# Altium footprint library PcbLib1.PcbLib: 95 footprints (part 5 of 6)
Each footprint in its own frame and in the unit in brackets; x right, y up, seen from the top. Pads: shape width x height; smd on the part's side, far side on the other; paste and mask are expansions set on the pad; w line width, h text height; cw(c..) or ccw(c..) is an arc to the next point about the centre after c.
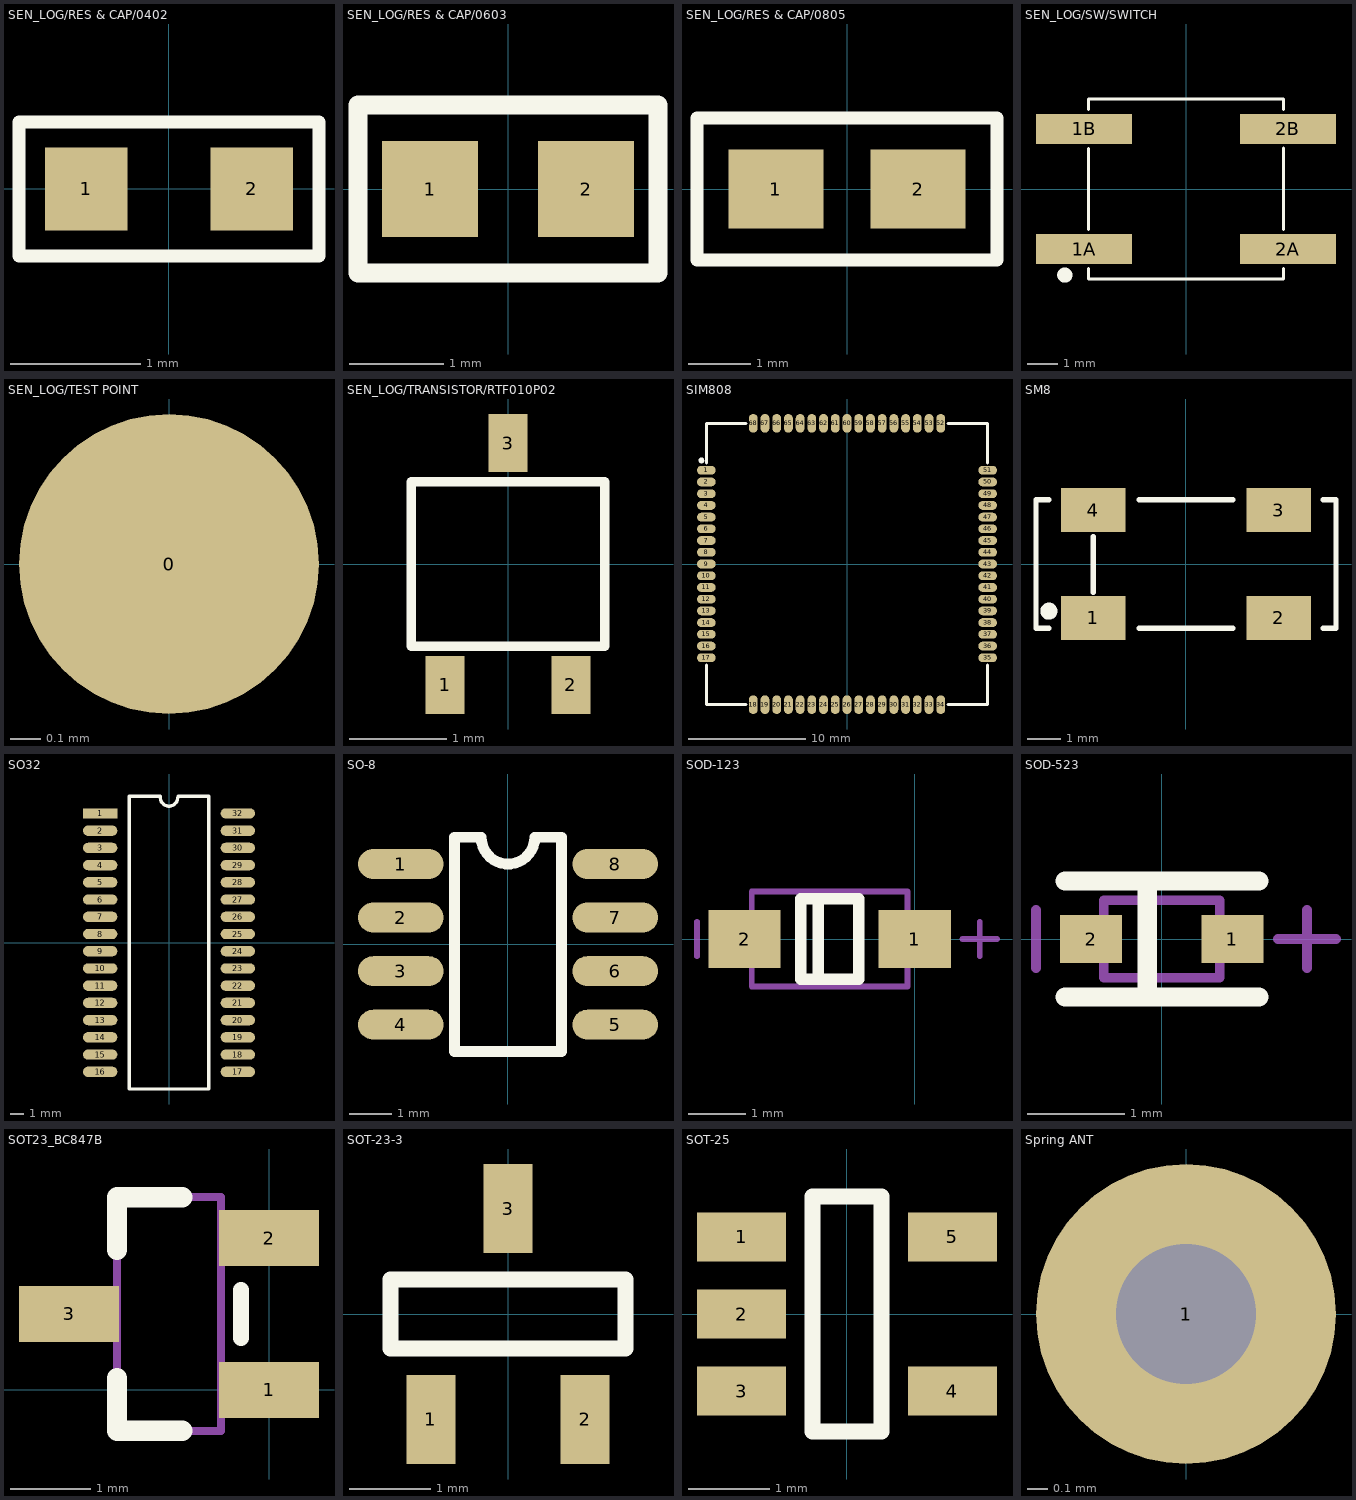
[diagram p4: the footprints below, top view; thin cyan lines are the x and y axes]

## SEN_LOG/RES & CAP/0402 [mm]
pads (2):
  rect 0.635x0.635 smd: 1(-0.635,0) 2(0.635,0)
Top Overlay:
  lines w0.1: -1.15,-0.513 -1.15,0.512 1.15,0.512 1.15,-0.513 -1.15,-0.513

## SEN_LOG/RES & CAP/0603 [mil]
pads (2):
  rect 40x40 smd: 1(-32.5,0) 2(32.5,0)
Top Overlay:
  lines w8: -62.5,-35 -62.5,35 62.5,35 62.5,-35 -62.5,-35

## SEN_LOG/RES & CAP/0805 [mil]
pads (2):
  rect 60x50 smd: 1(-45,0) 2(45,0)
Top Overlay:
  lines w8: 20,45 95,45 95,-45 20,-45 -95,-45 -95,45 25,45

## SEN_LOG/SW/SWITCH [mm]
pads (4):
  rect 3.2x1 smd mask+0.07: 1A(-3.4,-2) 1B(-3.4,2) 2A(3.4,-2) 2B(3.4,2)
Top Overlay:
  circle w0.254: c-4.039,-2.87 r0.127
  lines w0.1: -3.253,-2.643 -3.253,-2.997 3.247,-2.997 3.247,-2.646 ; -3.253,2.643 -3.253,3.003 3.247,3.003 3.247,2.646 ; -3.251,-1.346 -3.251,1.344 ; 3.247,-1.346 3.247,1.367

## SEN_LOG/TEST POINT [mm]
pads (1):
  round 1 smd: 0(0,0)

## SEN_LOG/TRANSISTOR/RTF010P02 [mm]
pads (3):
  rect 0.4x0.6 smd: 1(-0.65,-1.25) 2(0.65,-1.25) 3(0,1.25)
Top Overlay:
  lines w0.1: -1,-0.85 -1,0.85 1,0.85 1,-0.85 -1,-0.85

## SIM808 [mm]
pads (68):
  oval 1.6x0.75 smd: 1(-12,8) 2(-12,7) 3(-12,6) 4(-12,5) 5(-12,4) 6(-12,3) 7(-12,2) 8(-12,1) 9(-12,0) 10(-12,-1) 11(-12,-2) 12(-12,-3) 13(-12,-4) 14(-12,-5) 15(-12,-6) 16(-12,-7) 17(-12,-8) 35(12,-8) 36(12,-7) 37(12,-6) 38(12,-5) 39(12,-4) 40(12,-3) 41(12,-2) 42(12,-1) 43(12,0) 44(12,1) 45(12,2) 46(12,3) 47(12,4) 48(12,5) 49(12,6) 50(12,7) 51(12,8)
  oval 0.75x1.6 smd: 18(-8,-12) 19(-7,-12) 20(-6,-12) 21(-5,-12) 22(-4,-12) 23(-3,-12) 24(-2,-12) 25(-1,-12) 26(0,-12) 27(1,-12) 28(2,-12) 29(3,-12) 30(4,-12) 31(5,-12) 32(6,-12) 33(7,-12) 34(8,-12) 52(8,12) 53(7,12) 54(6,12) 55(5,12) 56(4,12) 57(3,12) 58(2,12) 59(1,12) 60(0,12) 61(-1,12) 62(-2,12) 63(-3,12) 64(-4,12) 65(-5,12) 66(-6,12) 67(-7,12) 68(-8,12)
Top Overlay:
  lines w0.25: -12.344,8.941 ccw(c-12.417,8.839) -12.292,8.839
  lines w0.254: -12,-8.636 -12,-12 -8.636,-12 ; -12,8.636 -12,12 -8.636,12 ; 8.636,-12 12,-12 12,-8.636 ; 8.636,12 12,12 12,8.636

## SM8 [mm]
pads (4):
  rect 1.9x1.3 smd: 1(-2.75,-1.6) 2(2.75,-1.6) 3(2.75,1.6) 4(-2.75,1.6)
Top Overlay:
  circle w0.254: c-4.064,-1.397 r0.127
  lines w0.152: -4.064,-1.905 -4.445,-1.905 -4.445,1.905 -4.064,1.905 ; -2.75,-0.838 -2.75,0.813 ; -1.397,-1.905 1.397,-1.905 ; -1.397,1.905 1.397,1.905 ; 4.064,-1.905 4.445,-1.905 4.445,-1.651 4.445,1.651 4.445,1.905 4.064,1.905

## SO32 [mil]
pads (32):
  rect 100x30 smd: 1(-200,375)
  oval 100x30 smd: 2(-200,325) 3(-200,275) 4(-200,225) 5(-200,175) 6(-200,125) 7(-200,75) 8(-200,25) 9(-200,-25) 10(-200,-75) 11(-200,-125) 12(-200,-175) 13(-200,-225) 14(-200,-275) 15(-200,-325) 16(-200,-375) 17(200,-375) 18(200,-325) 19(200,-275) 20(200,-225) 21(200,-175) 22(200,-125) 23(200,-75) 24(200,-25) 25(200,25) 26(200,75) 27(200,125) 28(200,175) 29(200,225) 30(200,275) 31(200,325) 32(200,375)
Top Overlay:
  lines w10: -116,-425 115,-425 115,425 27,425 ; -116,425 -26,425 ; -115,-425 -115,425 ; -25,421 ccw(c0,421) 25,421

## SO-8 [mil]
pads (8):
  oval 80x28 smd: 1(-100,75) 2(-100,25) 3(-100,-25) 4(-100,-75) 5(100,-75) 6(100,-25) 7(100,25) 8(100,75)
Top Overlay:
  lines w10: -28,100 -50,100 -50,-100 50,-100 50,100 25,100 cw(c0,100) -25,100

## SOD-123 [mm]
pads (2):
  rect 1.25x1 smd: 1(0,0) 2(-2.95,0)
Top Overlay:
  lines w0.2: -1.675,-0.7 -1.675,0.7 ; -1.975,-0.7 -1.975,0.7 -0.975,0.7 -0.975,-0.7 -1.975,-0.7
Mechanical 13:
  lines w0.1: -2.825,-0.825 -0.125,-0.825 -0.125,0.825 -2.825,0.825 -2.825,-0.825
Mechanical 15:
  lines w0.1: -3.775,-0.3 -3.775,0.3 ; 0.825,0 1.425,0 ; 1.125,-0.3 1.125,0.3
3D body: height 1.35, standoff 0, extent -3.325,-0.775 0.375,0.775

## SOD-523 [mm]
pads (2):
  rect 0.64x0.5 smd: 1(0.73,0) 2(-0.73,0)
Top Overlay:
  lines w0.2: -1,-0.6 1,-0.6 ; -1,0.6 1,0.6 ; -0.15,-0.575 -0.15,0.6
Mechanical 13:
  lines w0.1: -0.6,-0.4 -0.6,0.4 0.6,0.4 0.6,-0.4 -0.6,-0.4
Mechanical 15:
  lines w0.1: -1.3,-0.3 -1.3,0.3 ; 1.2,0 1.8,0 ; 1.5,-0.3 1.5,0.3
3D body: height 0.7, standoff 0, extent -0.8,-0.399 0.8,0.399

## SOT23_BC847B [mm]
pads (3):
  rect 1.25x0.7 smd: 1(0,0) 2(0,1.9) 3(-2.5,0.95)
Top Overlay:
  lines w0.2: -0.35,0.65 -0.35,1.25
  lines w0.254: -1.9,0.15 -1.9,-0.51 -1.085,-0.51 ; -1.085,2.41 -1.9,2.41 ; -1.9,1.75 -1.9,2.41 ; -1.9,1.75 -1.9,2.41 ; -1.9,1.75 -1.9,2.41
Mechanical 13:
  lines w0.1: -1.9,-0.51 -1.9,2.41 ; -1.9,-0.51 -0.6,-0.51 ; -1.9,-0.51 -0.6,-0.51 ; -1.9,-0.51 -1.9,2.41 ; -1.9,-0.51 -0.6,-0.51 ; -1.9,-0.51 -1.9,2.41 ; -1.9,2.41 -0.6,2.41 ; -1.9,2.41 -0.6,2.41 ; -1.9,2.41 -0.6,2.41 ; -0.6,-0.51 -0.6,2.41 ; -0.6,-0.51 -0.6,2.41 ; -0.6,-0.51 -0.6,2.41
3D body: height 1.3, standoff 0, extent -2.75,-0.55 0.25,2.45

## SOT-23-3 [mm]
pads (3):
  rect 0.6x1.1 smd: 1(-0.95,-1.3) 2(0.95,-1.3) 3(0,1.3)
Top Overlay:
  lines w0.2: -1.45,-0.425 -1.45,0.425 1.45,0.425 1.45,-0.425 -1.45,-0.425

## SOT-25 [mm]
pads (5):
  rect 1.1x0.6 smd: 1(-1.3,0.95) 2(-1.3,0) 3(-1.3,-0.95) 4(1.3,-0.95) 5(1.3,0.95)
Top Overlay:
  lines w0.2: -0.425,-1.45 0.425,-1.45 0.425,1.45 -0.425,1.45 -0.425,-1.45

## Spring ANT [mm]
pads (1):
  round 1.5 hole 0.7: 1(0,0)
